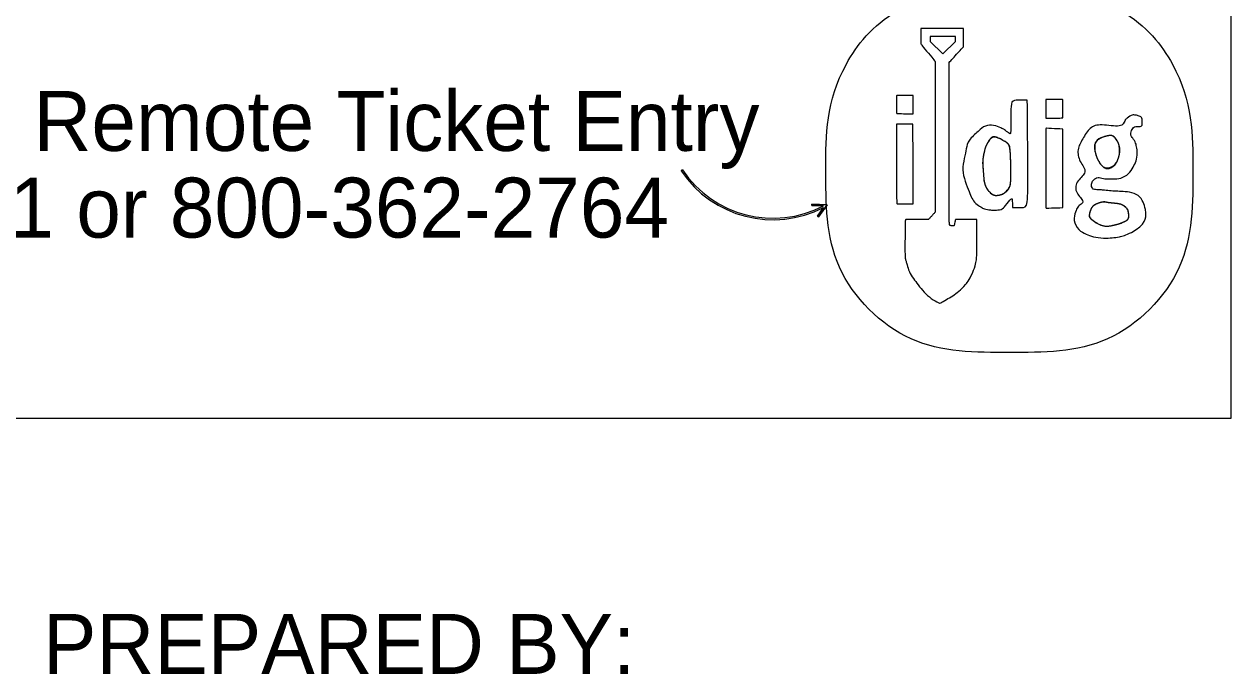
# Model space of a CAD drawing. Extents: x 0 to 70.2, y 0 to 31.4.
# Drawn here: x 42.259 to 45.077, y 11.816 to 13.334 of the extents above; entities that cross this region are included whole.
import ezdxf

# ---------------------------------------------------------------- set-up
doc = ezdxf.new("R2010")
doc.units = 0
for name, color, linetype in [('Default', 7, 'Continuous'), ('SH_Data', 7, 'Continuous'), ('SH_Text', 7, 'Continuous')]:
    doc.layers.add(name, color=color, linetype=linetype)

msp = doc.modelspace()

# ---------------------------------------------------------------- linework, layer by layer
at = {"layer": 'Default'}
for p, q in [((43.7965, 12.9935), (43.7934, 12.9915)), ((43.7934, 12.9915), (43.7965, 12.9935)), ((44.1119, 12.8852), (44.1262, 12.9056))]:
    msp.add_line(p, q, dxfattribs=at)
msp.add_lwpolyline([(44.4338, 13.2932), (44.4338, 13.3055), (44.3749, 13.3055), (44.3749, 13.2932), (44.4044, 13.2644)], close=True, dxfattribs=at)
for points in [[(44.1262, 12.9056), (44.1119, 12.8852), (44.1145, 12.8834), (44.1346, 12.9121), (44.0988, 12.9136), (44.0987, 12.9106), (44.1257, 12.9095)], [(44.1257, 12.9095), (44.0987, 12.9106), (44.0988, 12.9136), (44.1346, 12.9121), (44.1145, 12.8834), (44.1119, 12.8852)]]:
    msp.add_lwpolyline(points, dxfattribs=at)
for radius, start, end in [(0.2581, 213.7983, 297.2747), (0.2581, 213.7983, 297.2747), (0.2545, 213.7955, 297.5724), (0.2545, 213.7955, 297.5724)]:
    msp.add_arc((44.0079, 13.135), radius, start, end, dxfattribs=at)
for points, degree in [([(44.5599, 13.4242), (44.3231, 13.4242), (44.1312, 13.2323), (44.1312, 12.9955), (44.1312, 12.7587), (44.3231, 12.5667), (44.5599, 12.5667), (44.7967, 12.5667), (44.9887, 12.7587), (44.9887, 12.9955), (44.9887, 13.2323), (44.7967, 13.4242), (44.5599, 13.4242)], 3), ([(44.4762, 12.7589), (44.4688, 12.7398), (44.4574, 12.7236), (44.4413, 12.7099), (44.4279, 12.6984), (44.4128, 12.6908), (44.3976, 12.6815), (44.3974, 12.6815), (44.3974, 12.6815), (44.3973, 12.6815), (44.3771, 12.6924), (44.3606, 12.7075), (44.3468, 12.7252), (44.3356, 12.7396), (44.3256, 12.755), (44.3207, 12.7731), (44.3188, 12.7799), (44.3163, 12.7869), (44.3163, 12.7937), (44.3159, 12.8199), (44.3165, 12.846), (44.3166, 12.8722), (44.3166, 12.8736), (44.3173, 12.875), (44.3178, 12.8772), (44.3178, 12.8773), (44.3179, 12.8775), (44.318, 12.8775), (44.318, 12.8775), (44.3709, 12.8775), (44.3709, 12.8775), (44.371, 12.8775), (44.371, 12.8775), (44.3711, 12.8776), (44.3766, 12.8836), (44.3813, 12.8888), (44.3869, 12.895), (44.3869, 12.895), (44.387, 12.8952), (44.387, 12.8952), (44.387, 12.9013), (44.387, 12.9084), (44.387, 12.917), (44.387, 13.0279), (44.387, 13.1374), (44.387, 13.2463), (44.387, 13.2463), (44.387, 13.2464), (44.387, 13.2464), (44.3766, 13.2596), (44.3567, 13.2827), (44.3532, 13.288), (44.3532, 13.288), (44.3532, 13.2881), (44.3532, 13.2881), (44.3532, 13.2881), (44.3532, 13.3238), (44.3532, 13.3238), (44.3532, 13.3239), (44.3533, 13.3241), (44.3534, 13.3241), (44.3534, 13.3241), (44.4526, 13.3241), (44.4526, 13.3241), (44.4528, 13.3241), (44.4529, 13.3239), (44.4529, 13.3238), (44.4529, 13.3238), (44.4529, 13.2815), (44.4529, 13.2815), (44.4529, 13.2814), (44.4529, 13.2814), (44.4528, 13.2814), (44.4423, 13.2699), (44.4307, 13.2571), (44.4194, 13.2445), (44.4194, 13.2445), (44.4192, 13.2444), (44.4192, 13.2444), (44.4192, 13.2372), (44.4192, 13.2304), (44.4192, 13.2238), (44.4192, 13.1092), (44.4192, 12.9945), (44.4192, 12.8799), (44.4192, 12.8755), (44.4199, 12.869), (44.4203, 12.8657), (44.4204, 12.8644), (44.4215, 12.8633), (44.4228, 12.8632), (44.4228, 12.8632), (44.429, 12.8627), (44.429, 12.8627), (44.4301, 12.8626), (44.431, 12.8632), (44.4311, 12.8643), (44.4318, 12.8676), (44.4332, 12.8744), (44.4339, 12.8771), (44.4339, 12.8772), (44.434, 12.8773), (44.4341, 12.8773), (44.4341, 12.8773), (44.4834, 12.8773), (44.4834, 12.8773), (44.4835, 12.8773), (44.4837, 12.8772), (44.4837, 12.8771), (44.4837, 12.8582), (44.4837, 12.8397), (44.4837, 12.8211), (44.4837, 12.8161), (44.4839, 12.8112), (44.4839, 12.8062), (44.4842, 12.7899), (44.482, 12.7738), (44.4762, 12.7589)], 3), ([(44.2964, 13.1663), (44.2964, 13.1668), (44.2968, 13.1672), (44.2974, 13.1672), (44.3244, 13.1672), (44.3322, 13.1673), (44.3346, 13.1673), (44.3351, 13.1673), (44.3355, 13.1669), (44.3355, 13.1664), (44.3355, 13.1612), (44.3355, 13.1363), (44.3353, 13.1252), (44.3353, 13.1247), (44.3349, 13.1243), (44.3343, 13.1243), (44.3231, 13.1243), (44.3018, 13.1252), (44.2974, 13.1253), (44.2968, 13.1256), (44.2964, 13.126), (44.2964, 13.1264), (44.2964, 13.1264), (44.2964, 13.1663), (44.2964, 13.1663)], 3), ([(44.5675, 12.9053), (44.5675, 12.9053), (44.5665, 12.924), (44.5665, 12.9294), (44.5498, 12.9086), (44.5421, 12.8998), (44.5247, 12.8994), (44.5175, 12.8993), (44.4998, 12.9026), (44.4946, 12.9059), (44.4806, 12.9146), (44.4721, 12.9268), (44.4666, 12.9409), (44.4565, 12.9669), (44.4493, 12.9932), (44.4549, 13.021), (44.4596, 13.0437), (44.4631, 13.0623), (44.4887, 13.085), (44.5031, 13.0977), (44.5236, 13.0992), (44.542, 13.0907), (44.5477, 13.0881), (44.5597, 13.0789), (44.5636, 13.0755), (44.5636, 13.1029), (44.5636, 13.1283), (44.5636, 13.1561), (44.5788, 13.1561), (44.6019, 13.1565), (44.6019, 13.1565), (44.6019, 13.1565), (44.6035, 12.987), (44.6035, 12.9054), (44.592, 12.9053), (44.5675, 12.9053), (44.5675, 12.9053)], 3), ([(44.6849, 13.1153), (44.6849, 13.115), (44.6846, 13.1147), (44.6844, 13.1147), (44.6726, 13.1147), (44.6496, 13.1143), (44.6459, 13.1143), (44.6458, 13.1143), (44.6455, 13.1145), (44.6455, 13.1149), (44.6455, 13.1149), (44.6455, 13.1575), (44.6455, 13.1575), (44.6455, 13.1578), (44.6458, 13.1581), (44.6461, 13.1581), (44.6763, 13.1581), (44.683, 13.1577), (44.6845, 13.1575), (44.6848, 13.1575), (44.6849, 13.1573), (44.6849, 13.157), (44.6849, 13.157), (44.6849, 13.1153), (44.6849, 13.1153)], 3), ([(44.8451, 12.8475), (44.8318, 12.8411), (44.8161, 12.8363), (44.8007, 12.835), (44.7809, 12.8334), (44.7542, 12.8366), (44.74, 12.843), (44.721, 12.8518), (44.7081, 12.8755), (44.715, 12.8963), (44.7187, 12.9075), (44.7277, 12.913), (44.736, 12.9195), (44.7118, 12.9426), (44.7165, 12.9691), (44.7449, 12.9878), (44.7229, 13.0126), (44.7175, 13.0416), (44.7307, 13.0647), (44.7475, 13.0941), (44.7726, 13.1013), (44.8237, 13.0912), (44.8307, 13.1109), (44.8307, 13.1109), (44.8458, 13.1224), (44.8524, 13.1216), (44.8612, 13.1204), (44.8702, 13.1169), (44.8705, 13.1079), (44.8705, 13.1015), (44.8705, 13.0937), (44.8541, 13.0961), (44.8456, 13.0894), (44.8427, 13.0745), (44.8454, 13.0709), (44.8549, 13.0587), (44.857, 13.0479), (44.8598, 13.033), (44.8565, 13.0132), (44.8493, 13.0006), (44.8397, 12.9837), (44.8208, 12.9725), (44.8006, 12.9725), (44.7924, 12.9725), (44.7803, 12.9725), (44.7652, 12.977), (44.7616, 12.9738), (44.7552, 12.9687), (44.7536, 12.9652), (44.7513, 12.9602), (44.7519, 12.9544), (44.7544, 12.9503), (44.7564, 12.9471), (44.7722, 12.9469), (44.7779, 12.9462), (44.7936, 12.9445), (44.8093, 12.9437), (44.825, 12.9428), (44.8462, 12.9414), (44.8669, 12.9313), (44.8742, 12.9132), (44.8793, 12.9001), (44.8793, 12.8643), (44.8451, 12.8475)], 3), ([(44.2975, 12.9148), (44.2959, 12.9232), (44.2964, 13.0389), (44.2964, 13.0996), (44.2964, 13.1), (44.2967, 13.1002), (44.2971, 13.1002), (44.3098, 13.1002), (44.3302, 13.1002), (44.3339, 13.1002), (44.3343, 13.1002), (44.3346, 13.1), (44.3346, 13.0996), (44.3347, 13.0902), (44.3355, 12.9731), (44.3355, 12.9149), (44.3355, 12.9145), (44.3353, 12.9142), (44.3349, 12.9142), (44.3349, 12.9142), (44.2981, 12.9142), (44.2981, 12.9142), (44.2977, 12.9142), (44.2975, 12.9145), (44.2975, 12.9148)], 3), ([(44.6849, 12.9059), (44.6849, 12.9055), (44.6846, 12.9053), (44.6842, 12.9053), (44.6842, 12.9053), (44.6462, 12.9042), (44.6462, 12.9042), (44.6459, 12.9042), (44.6455, 12.9045), (44.6455, 12.9049), (44.6455, 12.9049), (44.6455, 13.0899), (44.6455, 13.0899), (44.6455, 13.0903), (44.6458, 13.0906), (44.6462, 13.0906), (44.6462, 13.0906), (44.6842, 13.0889), (44.6842, 13.0889), (44.6846, 13.0889), (44.6849, 13.0886), (44.6849, 13.0882), (44.6849, 13.0882), (44.6849, 12.9059), (44.6849, 12.9059)], 3), ([(44.5451, 13.0625), (44.5597, 13.0546), (44.5618, 13.0415), (44.5625, 13.0298), (44.5635, 13.0089), (44.564, 12.988), (44.5631, 12.9672), (44.5625, 12.9528), (44.5483, 12.9381), (44.5391, 12.9353), (44.5321, 12.9334), (44.5202, 12.9347), (44.5121, 12.9434), (44.5068, 12.9492), (44.5009, 12.9649), (44.5004, 12.9724), (44.4985, 12.9953), (44.4969, 13.0184), (44.5026, 13.0411), (44.5034, 13.0446), (44.5047, 13.048), (44.5063, 13.0512), (44.5149, 13.0686), (44.5276, 13.0723), (44.5451, 13.0625)], 3), ([(44.5063, 13.0512), (44.5047, 13.048), (44.5034, 13.0446), (44.5026, 13.0411)], 2), ([(44.5451, 13.0625), (44.5276, 13.0723), (44.5149, 13.0686), (44.5063, 13.0512)], 2), ([(44.5625, 13.0298), (44.5618, 13.0415), (44.5597, 13.0546), (44.5451, 13.0625)], 2), ([(44.8126, 13.0155), (44.8073, 13.0012), (44.7804, 12.9929), (44.7682, 13.0146), (44.7601, 13.0291), (44.7574, 13.0628), (44.7808, 13.0706), (44.789, 13.0734), (44.8036, 13.0742), (44.8106, 13.0635), (44.8167, 13.0539), (44.8191, 13.0325), (44.8126, 13.0155)], 3), ([(44.7808, 13.0706), (44.7574, 13.0628), (44.7601, 13.0291), (44.7682, 13.0146)], 2), ([(44.8106, 13.0635), (44.8036, 13.0742), (44.789, 13.0734), (44.7808, 13.0706)], 2), ([(44.8126, 13.0155), (44.8191, 13.0325), (44.8167, 13.0539), (44.8106, 13.0635)], 2), ([(44.5026, 13.0411), (44.4969, 13.0184), (44.4985, 12.9953), (44.5004, 12.9724)], 2), ([(44.5631, 12.9672), (44.564, 12.988), (44.5635, 13.0089), (44.5625, 13.0298)], 2), ([(44.7682, 13.0146), (44.7804, 12.9929), (44.8073, 13.0012), (44.8126, 13.0155)], 2), ([(44.5004, 12.9724), (44.5009, 12.9649), (44.5068, 12.9492), (44.5121, 12.9434)], 2), ([(44.5391, 12.9353), (44.5483, 12.9381), (44.5625, 12.9528), (44.5631, 12.9672)], 2), ([(44.5121, 12.9434), (44.5202, 12.9347), (44.5321, 12.9334), (44.5391, 12.9353)], 2), ([(44.8319, 12.9056), (44.8371, 12.9011), (44.8379, 12.8958), (44.8384, 12.8923), (44.8408, 12.8785), (44.8248, 12.8705), (44.8171, 12.868), (44.803, 12.8635), (44.777, 12.8604), (44.7573, 12.8738), (44.7468, 12.8808), (44.7463, 12.8902), (44.7495, 12.899), (44.7516, 12.9051), (44.7574, 12.911), (44.7624, 12.9133), (44.7772, 12.9199), (44.7924, 12.9164), (44.806, 12.9153), (44.8149, 12.9145), (44.8252, 12.9116), (44.8319, 12.9056)], 3), ([(44.7624, 12.9133), (44.7574, 12.911), (44.7516, 12.9051), (44.7495, 12.899)], 2), ([(44.806, 12.9153), (44.7924, 12.9164), (44.7772, 12.9199), (44.7624, 12.9133)], 2), ([(44.8319, 12.9056), (44.8252, 12.9116), (44.8149, 12.9145), (44.806, 12.9153)], 2), ([(44.7495, 12.899), (44.7463, 12.8902), (44.7468, 12.8808), (44.7573, 12.8738)], 2), ([(44.8171, 12.868), (44.8248, 12.8705), (44.8408, 12.8785), (44.8384, 12.8923)], 2), ([(44.8384, 12.8923), (44.8379, 12.8958), (44.8371, 12.9011), (44.8319, 12.9056)], 2), ([(44.7573, 12.8738), (44.777, 12.8604), (44.803, 12.8635), (44.8171, 12.868)], 2)]:
    msp.add_open_spline(points, degree=degree, dxfattribs=at)
at = {"layer": 'SH_Data'}
msp.add_lwpolyline([(40.2257, 14.6673), (45.0774, 14.6673), (45.0774, 12.4128), (40.2257, 12.4128)], close=True, dxfattribs=at)

# ---------------------------------------------------------------- texts
for s, p in [('Remote Ticket Entry', (42.2806, 13.0378)), ('To call dial 8-1-1 or 800-362-2764', (40.9446, 12.8353))]:
    msp.add_text(s, height=0.14, dxfattribs=at).set_placement(p)
at = {"layer": 'SH_Text'}
msp.add_text('PLAN PREPARED BY:', height=0.14, dxfattribs=at).set_placement((41.7615, 11.8158))

doc.saveas('drawing.dxf')
